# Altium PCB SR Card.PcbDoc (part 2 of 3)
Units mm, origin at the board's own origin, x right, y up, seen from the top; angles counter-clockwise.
Board outline 110.01 x 84.94 mm, 10 copper layers (Top Layer, Layer 2, Layer 3, Layer 4, Layer 5, Layer 6, Layer 7, Layer 8, Layer 9, Bottom Layer), stack 2.452 mm thick; 165 components, 84 nets, 582 pads, 1965 vias.
Unrouted connection lines stored in the file: 24.
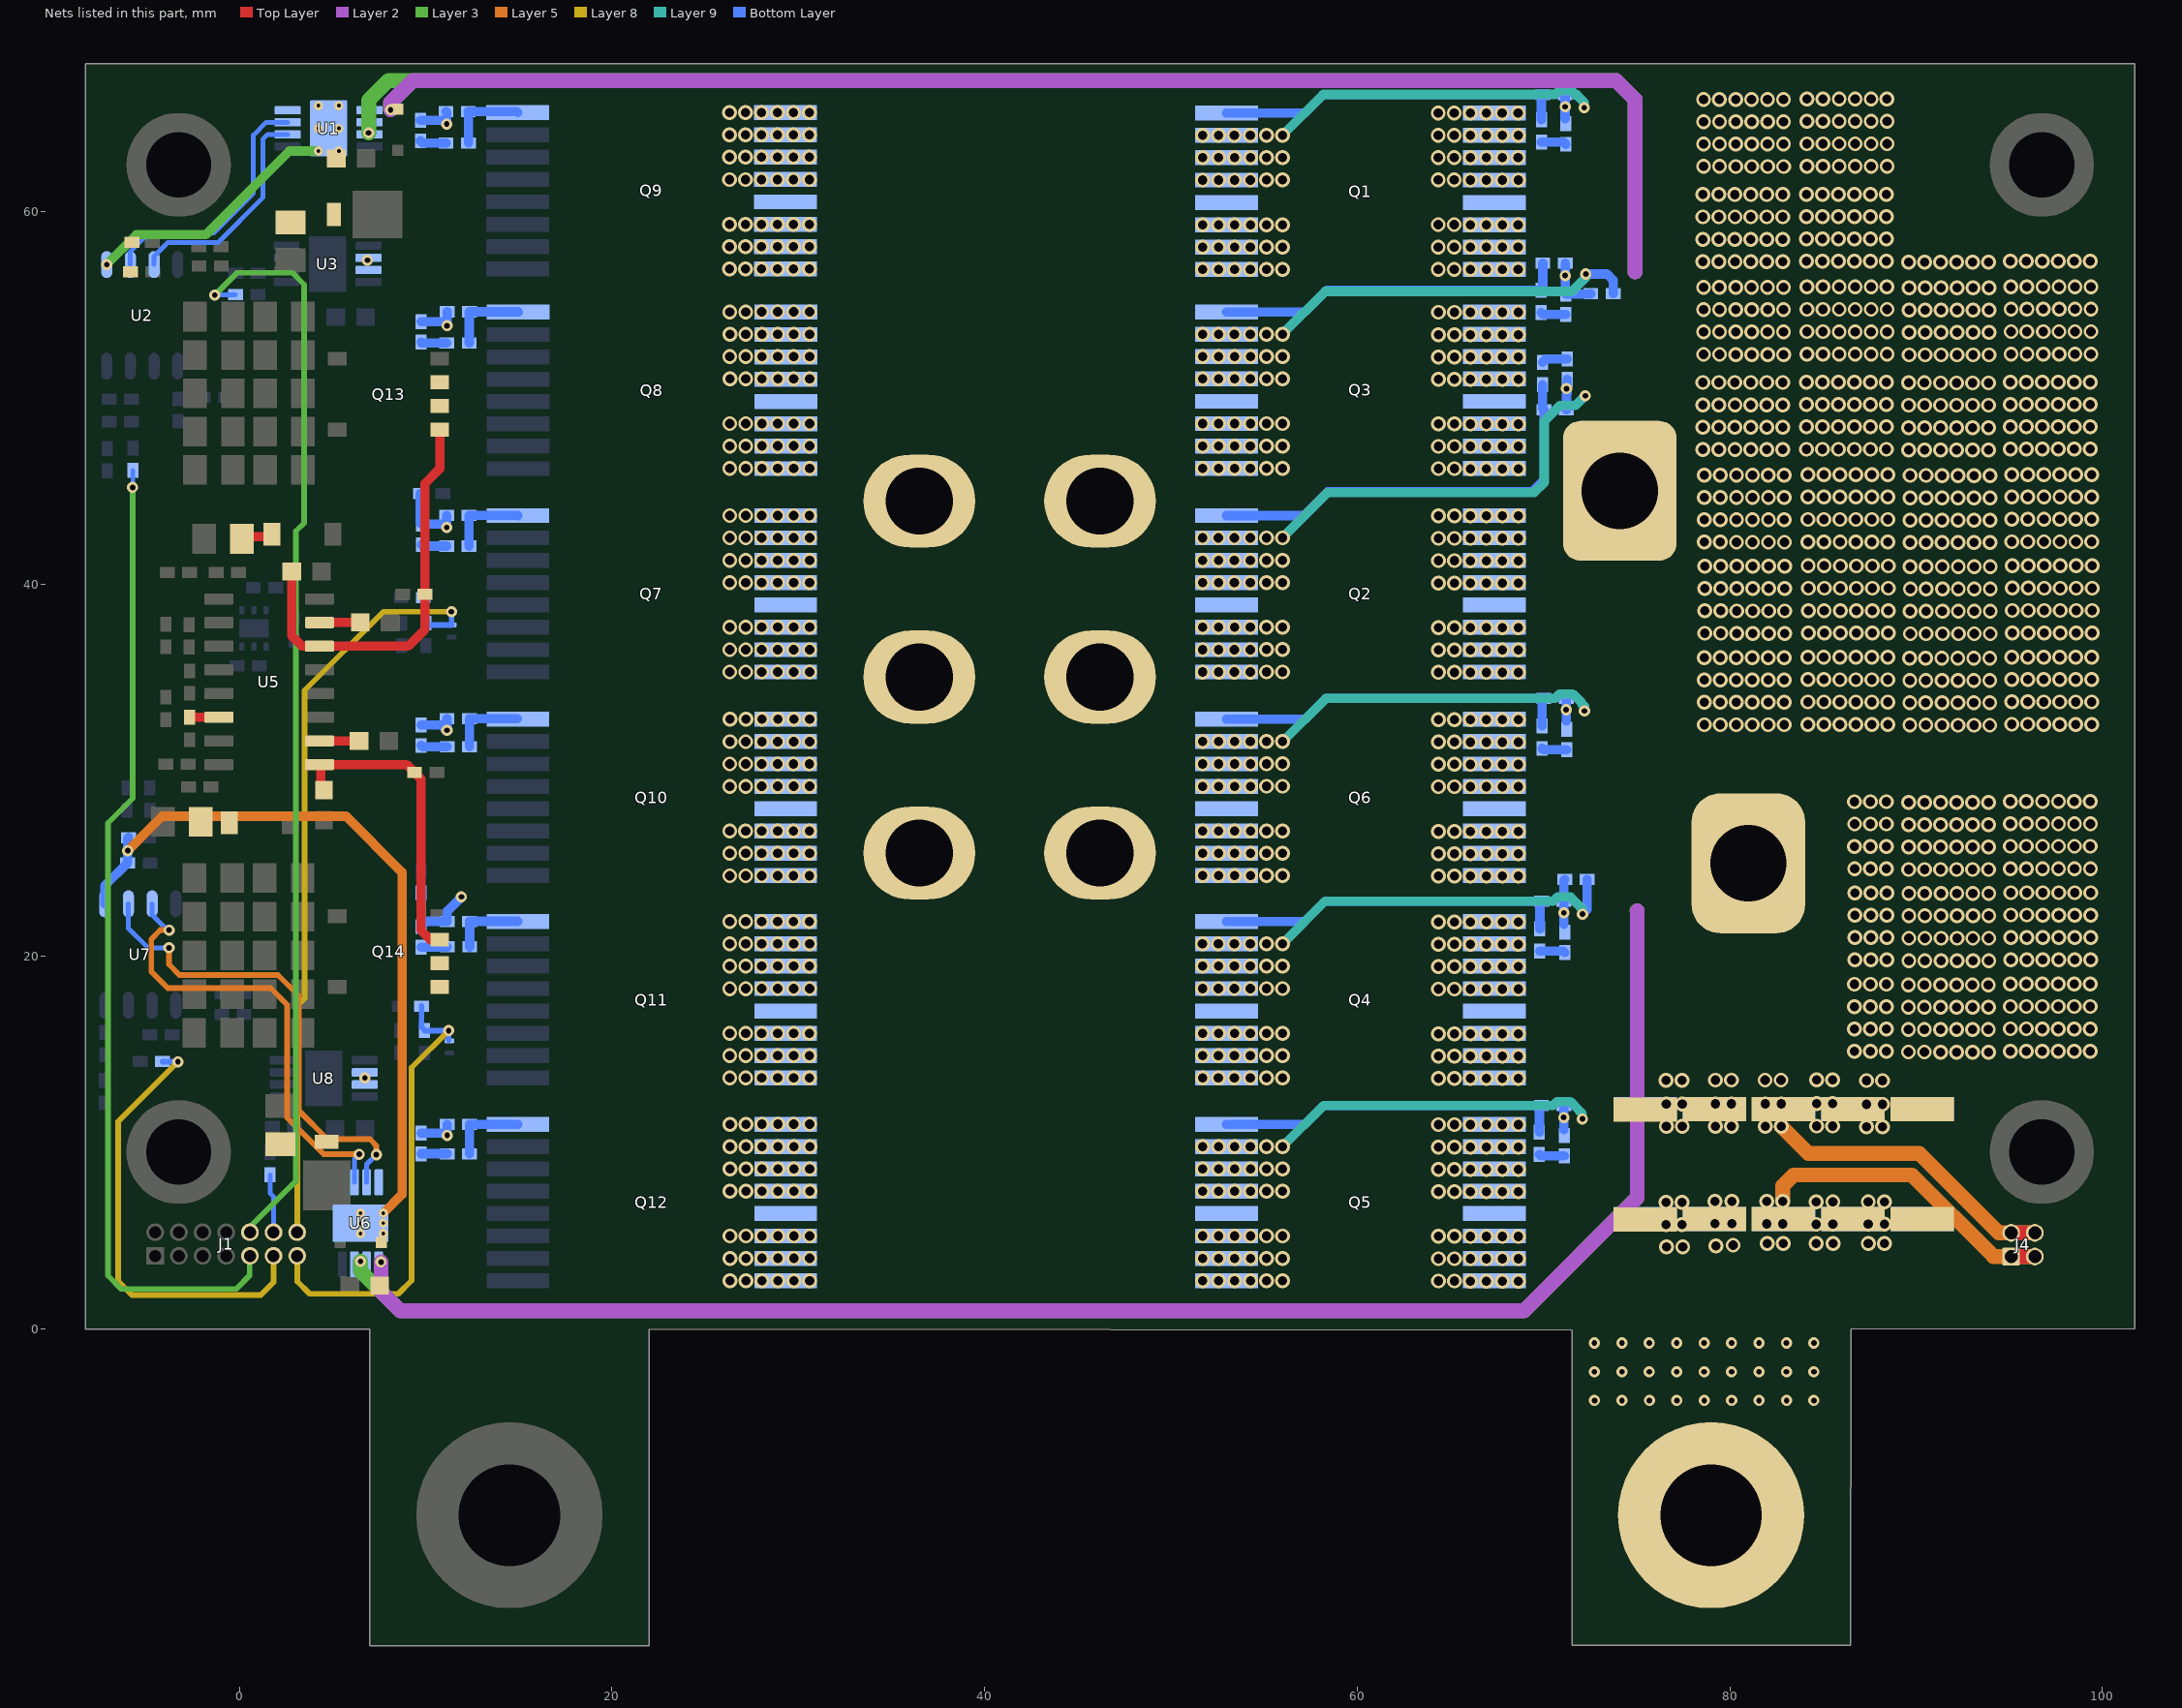
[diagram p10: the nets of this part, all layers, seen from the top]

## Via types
v1: diameter 0.8, hole 0.5, Top Layer to Bottom Layer, 1795 vias
v2: diameter 0.6, hole 0.3, Top Layer to Bottom Layer, 144 vias
v3: diameter 0.5, hole 0.2, Top Layer to Bottom Layer, 26 vias

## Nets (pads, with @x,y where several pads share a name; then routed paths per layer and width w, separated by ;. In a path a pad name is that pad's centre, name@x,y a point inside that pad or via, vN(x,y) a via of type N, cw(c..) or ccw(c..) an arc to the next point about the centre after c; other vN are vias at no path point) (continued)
NetD1_2: D1.2 R7.1 | length 3.1
  Top Layer w0.254: R7.1@0.146,42.426 0.383,42.663 D1.2@1.745,42.663
  Top Layer w0.5: R7.1@0.265,42.545 D1.2@1.628,42.545
NetD2_2: D2.2 R21.2
NetD3_2: D3.2 R35.1 | length 1.4
  Bottom Layer w0.5: R35.1@69.888,63.722 71.086,63.722 D3.2@71.203,63.604
NetD4_2: D4.2 R60.2 | length 1.4
  Bottom Layer w0.5: R60.2@69.926,31.169 69.998,31.098 D4.2@71.249,31.098
NetD5_2: D5.2 R63.1 | length 1.4
  Bottom Layer w0.5: R63.1@69.948,51.889 70.144,52.085 D5.2@71.281,52.085
NetD6_2: D6.2 R66.2 | length 1.4
  Bottom Layer w0.5: R66.2@69.781,9.367 69.855,9.294 D6.2@71.124,9.294
NetD7_2: D7.2 R62.1 | length 1.4
  Bottom Layer w0.5: R62.1@69.866,54.576 69.979,54.463 D7.2@71.2,54.463
NetD8_2: D8.2 R61.2 | length 1.4
  Bottom Layer w0.5: R61.2@69.807,20.28 71.066,20.28 D8.2@71.141,20.204
NetD9_2: D9.2 R64.1 | length 1.4
  Bottom Layer w0.5: D9.2@9.784,42.11 9.862,42.031 R64.1@11.126,42.031
NetD10_2: D10.2 R65.2 | length 1.4
  Bottom Layer w0.5: D10.2@9.767,9.409 R65.2@11.156,9.409
NetD11_2: D11.2 R67.1 | length 1.4
  Bottom Layer w0.5: D11.2@9.753,52.98 9.798,52.935 R67.1@11.142,52.935
NetD12_2: D12.2 R68.2 | length 1.4
  Bottom Layer w0.5: D12.2@9.756,20.502 11.156,20.502 R68.2@11.166,20.512
NetD13_2: D13.2 R70.1 | length 1.4
  Bottom Layer w0.5: D13.2@9.72,63.784 9.837,63.667 R70.1@11.097,63.667
NetD14_2: D14.2 R71.2 | length 1.4
  Bottom Layer w0.5: D14.2@9.765,31.324 9.829,31.26 R71.2@11.162,31.26
NetD15_2: D15.2 R5.1
NetD17_2: D17.2 R69.1
NetQ1_8: Q1.8 R1.2 R35.2 | length 18.8
  Bottom Layer w0.5: Q1.8@52.983,65.28 52.992,65.272 57.18,65.272 58.167,66.259 R1.2@69.963,66.259 69.888,66.183 R35.2@69.888,64.922
NetQ2_8: Q2.8 R9.2 R63.2 | length 23
  Bottom Layer w0.5: Q2.8@52.983,43.671 57.154,43.671 58.424,44.941 69.379,44.941 70.031,45.593 R9.2@70.031,49.34 69.948,49.423 R63.2@69.948,50.689
NetQ3_8: Q3.8 R15.2 R62.2 | length 18.8
  Bottom Layer w0.5: Q3.8@52.983,54.604 57.189,54.604 58.362,55.776 R62.2@69.866,55.776 69.965,55.876 R15.2@69.965,57.211
NetQ4_8: Q4.8 R16.1 R61.1 | length 18.9
  Bottom Layer w0.5: Q4.8@52.983,21.874 57.188,21.874 58.283,22.969 R16.1@69.9,22.969 69.807,22.876 R61.1@69.807,21.48
NetQ5_8: Q5.8 R10.1 R66.1 | length 18.8
  Bottom Layer w0.5: Q5.8@52.983,10.993 57.192,10.993 58.206,12.006 R10.1@69.885,12.006 69.781,11.902 R66.1@69.781,10.567
NetQ6_8: Q6.8 R2.1 R60.1 | length 19
  Bottom Layer w0.5: Q6.8@52.983,32.734 57.191,32.734 58.309,33.852 R2.1@70.016,33.852 69.926,33.762 R60.1@69.926,32.369
NetQ7_8: Q7.8 R30.2 R64.2 | length 4.3
  Bottom Layer w0.5: R64.2@12.326,42.031 12.326,43.674 R30.2@12.337,43.685 14.939,43.685 Q7.8@14.954,43.671
NetQ8_8: Q8.8 R36.2 R67.2 | length 4.3
  Bottom Layer w0.5: R67.2@12.342,52.935 12.342,54.601 R36.2@12.35,54.609 14.954,54.609 Q8.8@14.976,54.588
NetQ9_8: Q9.8 R42.2 R70.2 | length 4.4
  Bottom Layer w0.5: R70.2@12.297,63.667 12.297,65.36 R42.2@12.293,65.365 14.891,65.365 Q9.8@14.946,65.31
NetQ10_8: Q10.8 R39.1 R71.1 | length 4.1
  Bottom Layer w0.5: R71.1@12.362,31.26 12.362,32.749 R39.1@12.346,32.764 Q10.8@14.924,32.764
NetQ11_8: Q11.8 R33.1 R68.1 | length 4
  Bottom Layer w0.5: R68.1@12.366,20.512 12.366,21.883 R33.1@12.364,21.884 14.944,21.884 Q11.8@14.954,21.874
NetQ12_8: Q12.8 R26.1 R65.1 | length 4.2
  Bottom Layer w0.5: R65.1@12.356,9.409 R26.1@12.356,10.992 ; R26.1@12.356,10.992 Q12.8@14.954,10.993
NetR18_1: R18.1 U5.15 | length 2.2
  Top Layer w0.5: U5.15@4.306,37.924 4.325,37.943 R18.1@6.491,37.943
NetR37_1: R37.1 U5.10 | length 2.1
  Top Layer w0.5: U5.10@4.306,31.574 6.424,31.574 R37.1@6.432,31.566
NetR51_1: R51.1 U5.6 | length 1.6
  Top Layer w0.5: R51.1@-2.679,32.836 -2.671,32.844 U5.6@-1.094,32.844
NetU1_2: U1.2 U2.7 | length 12.2
  Bottom Layer w0.254: U2.7@-4.576,57.144 -4.576,57.578 -3.828,58.326 -1.141,58.326 1.263,60.73 1.263,63.874 1.52,64.131 U1.2@2.597,64.131
NetU1_3: U1.3 U2.6 | length 13.8
  Bottom Layer w0.254: U2.6@-5.846,57.144 -5.846,57.846 -4.86,58.832 -1.377,58.832 0.757,60.966 0.757,64.088 1.449,64.781 U1.3@2.597,64.781
NetU6_2: U6.2 U7.7 | length 25.1
  Layer 5 w0.3: v2(-3.769,21.416) -4.239,21.416 -4.722,20.933 -4.722,19.182 -3.837,18.296 1.682,18.296 2.571,17.407 2.571,11.345 4.527,9.39 4.527,9.383 v2(6.437,9.383)
  Bottom Layer w0.254: U7.7@-4.678,22.824 -4.678,22.225 v2@-3.819,21.366 ; U6.2@6.184,7.871 6.184,9.131 v2(6.437,9.383)
NetU6_3: U6.3 U7.6 | length 25.8
  Layer 5 w0.3: v2(-3.772,20.461) -3.772,19.57 -3.211,19.009 2.079,19.009 3.209,17.879 3.209,11.712 4.733,10.188 7.008,10.188 7.355,9.841 v2(7.355,9.36)
  Bottom Layer w0.254: U7.6@-5.948,22.824 -5.948,21.497 -4.912,20.461 v2(-3.772,20.461) ; U6.3@6.834,7.871 6.834,8.839 v2(7.355,9.36)
"SR1 HO": D3.1 D5.1 D7.1 R1.1 R9.1 R11.2 R15.1 U1.6 U1.7 | length 85.4
  Layer 3 w0.8: v2(6.941,64.214) 6.941,65.957 8.013,67.029 73.9,67.029 74.908,66.021 74.908,56.76
  Bottom Layer w0.5: D3.1@71.163,64.982 v2(71.163,65.62) R1.1@71.163,66.259 ; D7.1@71.165,55.895 v2(71.165,56.553) R15.1@71.165,57.211 ; D7.1@71.2,55.563 72.516,55.563 R11.2@72.539,55.586 ; R9.1@71.231,49.34 71.238,49.347 71.238,50.183 71.281,50.225 D5.1@71.281,50.985
  other v2: 71.238,50.483
"SR1 LO": D9.1 D11.1 D13.1 R30.1 R36.1 R42.1 R45.2 U3.6 U3.7 | length 8.2
  Bottom Layer w0.5: R45.2@9.719,44.858 9.719,43.274 D9.1@9.784,43.21 10.957,43.21 v2(11.137,43.029) R30.1@11.137,43.685 ; D13.1@9.72,64.884 10.942,64.884 v2(11.133,64.693) 11.133,65.325 R42.1@11.093,65.365 ; D11.1@9.753,54.08 10.933,54.08 v2(11.15,53.862) R36.1@11.15,54.609
  other v2: 6.882,57.384
SR1_HS_PWM: J1.9 R48.1 | length 53.1
  Layer 3 w0.3: v2(-5.723,45.181) -5.723,28.488 -7.051,27.16 -7.051,2.865 -6.339,2.152 -0.161,2.152 0.559,2.872 0.559,3.916 J1.9@0.569,3.926
  Bottom Layer w0.24: v2(-5.723,45.181) -5.715,45.189 R48.1@-5.715,46.102
SR1_LS_PWM: J1.10 R12.1 | length 58.8
  Layer 3 w0.3: v2(-1.316,55.509) -0.122,56.703 2.849,56.703 3.481,56.071 3.481,43.266 3.044,42.829 3.044,7.947 0.569,5.472 J1.10@0.569,5.196
  Bottom Layer w0.24: v2(-1.316,55.509) -1.306,55.518 -0.213,55.518 R12.1@-0.203,55.528
"SR2 HO": D4.1 D6.1 D8.1 R2.2 R10.2 R14.1 R16.2 U6.6 U6.7 | length 92.8
  Layer 3 w0.8: v2(6.503,3.626) 6.503,3.123 8.657,0.969 68.939,0.969 75.032,7.063 75.032,22.446 75.023,22.454
  Bottom Layer w0.5: D6.1@71.085,10.713 v2(71.085,11.36) R10.2@71.085,12.006 ; 71.1,21.716 v2(71.1,22.343) R16.2@71.1,22.969 71.1,24.091 R14.1@71.149,24.14 ; 71.216,32.64 v2(71.216,33.246) R2.2@71.216,33.852
"SR2 LO": D10.1 D12.1 D14.1 R26.2 R33.2 R39.2 R54.1 U8.6 U8.7 | length 9.1
  Bottom Layer w0.5: R54.1@9.755,23.398 9.755,21.603 D12.1@9.756,21.602 10.039,21.884 R33.2@11.164,21.884 11.164,22.438 v2(11.922,23.195) ; D14.1@9.765,32.424 10.86,32.424 v2(11.146,32.138) R39.2@11.146,32.764 ; D10.1@9.767,10.509 11.044,10.509 v2(11.156,10.397) R26.2@11.156,10.992
  other v2: 6.741,13.478
SR2_HS_PWM: J1.11 R49.1 | length 24.1
  Layer 8 w0.3: v2(-3.293,14.344) -6.5,11.138 -6.5,2.567 -5.754,1.822 1.149,1.822 1.839,2.511 J1.11@1.839,3.926
  Bottom Layer w0.3: R49.1@-4.126,14.355 v2@-3.507,14.355
SR2_LS_PWM: J1.12 R53.1 | length 3.2
  Bottom Layer w0.254: R53.1@1.657,8.277 1.657,7.284 1.831,7.109 1.833,7.109 1.839,7.103 J1.12@1.839,5.196
T_LV_1: C28.1 J1.13 R44.1 RT1.2 | length 25.5
  Layer 8 w0.3: J1.13@3.109,3.926 3.109,2.557 3.781,1.885 8.529,1.885 9.247,2.603 9.247,14.033 v2(11.233,16.02)
  Bottom Layer w0.3: R44.1@9.781,17.335 9.781,16.206 C28.1@9.945,16.043 ; C28.1@9.945,16.02 v2(11.233,16.02) RT1.2@11.233,15.51
T_LV_2: C19.1 J1.14 R22.1 RT2.2 | length 42.4
  Layer 8 w0.3: J1.14@3.109,5.196 3.109,17.346 3.511,17.747 3.511,34.281 7.735,38.506 v2(11.382,38.506)
  Bottom Layer w0.3: R22.1@9.876,39.256 9.876,38.027 C19.1@10.007,37.895 10.108,37.794 RT2.2@11.407,37.794 ; v2(11.382,38.506) 11.39,38.498 RT2.2@11.39,37.82
VBIAS: J2.1 J4.1 J4.3 R29.2 R40.2 R41.2 R46.2 R47.2 R50.2 R56.2 R57.2 R58.2 R59.2 | length 17.7
  Top Layer w0.8: J4.1@95.102,3.891 J4.3@96.372,3.891
  Layer 5 w0.8: v1(82.85,6.843) 82.85,7.696 83.422,8.269 89.777,8.269 94.155,3.891 J4.1@95.102,3.891 J4.3@96.372,3.891
  other v1: 76.61,4.404 77.476,4.402 79.252,4.463 80.176,4.499 82.013,4.582 82.869,4.582 84.631,4.582 85.537,4.589 87.433,4.6 88.298,4.598 76.574,5.605 77.43,5.605 84.628,5.616 85.534,5.623 79.199,5.647 81.995,5.641 82.852,5.641 87.43,5.634 88.295,5.632 80.107,5.654 76.572,6.805 77.429,6.805 84.627,6.818 81.994,6.843 85.532,6.823 87.428,6.834 88.293,6.832 79.197,6.847 80.105,6.856
  other v2: 72.741,-3.837 74.213,-3.837 75.685,-3.837 77.157,-3.837 78.629,-3.837 80.101,-3.837 81.574,-3.837 83.046,-3.837 84.518,-3.837 72.736,-2.295 74.208,-2.295 75.68,-2.295 77.153,-2.295 78.625,-2.295 80.097,-2.295 81.569,-2.295 83.041,-2.295 84.514,-2.295 72.736,-0.75 74.208,-0.75 75.68,-0.75 77.153,-0.75 78.625,-0.75 80.097,-0.75 81.569,-0.75 83.041,-0.75 84.514,-0.75
VOUT: J4.2 J4.4 pad.4@81,25 R29.1 R40.1 R41.1 R46.1 R47.1 R50.1 R56.1 R57.1 R58.1 R59.1 | length 17.3
  Top Layer w0.8: J4.2@95.102,5.161 J4.4@96.372,5.161
  Layer 5 w0.8: v1(82.759,10.884) 84.211,9.433 90.168,9.433 94.44,5.161 J4.2@95.102,5.161 J4.4@96.372,5.161
  other v1: 76.595,10.873 77.452,10.873 87.34,10.861 88.197,10.861 79.237,10.884 80.093,10.884 81.903,10.884 84.665,10.893 85.521,10.893 76.594,12.075 77.45,12.075 87.338,12.061 88.195,12.061 79.236,12.087 80.092,12.087 81.901,12.087 82.758,12.087 84.663,12.093 85.519,12.093 87.331,13.334 88.188,13.334 76.587,13.349 77.443,13.349 79.229,13.36 80.085,13.36 81.894,13.36 82.751,13.36 84.656,13.367 85.512,13.367 89.589,14.869 90.445,14.869 91.311,14.866 92.167,14.866 93.024,14.866 93.88,14.866 86.69,14.906 87.547,14.906 88.403,14.906 95.057,14.913 95.913,14.913 96.778,14.911 97.635,14.911 98.491,14.911 99.348,14.911 89.588,16.071 90.444,16.071 91.309,16.069 92.166,16.069 93.022,16.069 93.879,16.069 86.689,16.108 87.545,16.108 88.402,16.108 95.055,16.115 95.912,16.115 96.777,16.113 97.633,16.113 98.49,16.113 99.346,16.113 89.588,17.271 90.445,17.271 91.31,17.269 92.166,17.269 93.023,17.269 93.879,17.269 86.689,17.308 87.546,17.308 88.402,17.308 95.056,17.315 95.912,17.315 96.778,17.313 97.634,17.313 98.491,17.313 99.347,17.313 89.586,18.471 90.443,18.471 91.308,18.469 92.164,18.469 93.021,18.469 93.877,18.469 86.687,18.508 87.544,18.508 88.4,18.508 95.054,18.515 95.91,18.515 96.776,18.513 97.632,18.513 98.489,18.513 99.345,18.513 89.614,19.778 90.47,19.778 91.335,19.775 92.192,19.775 93.048,19.775 93.905,19.775 86.715,19.815 87.571,19.815 88.428,19.815 95.081,19.822 95.938,19.822 96.803,19.819 97.66,19.819 98.516,19.819 99.373,19.819 89.612,20.98 90.469,20.98 91.334,20.977 92.19,20.977 93.047,20.977 93.903,20.977 86.714,21.017 87.57,21.017 88.427,21.017 95.08,21.024 95.937,21.024 96.802,21.022 97.658,21.022 98.515,21.022 99.371,21.022 89.613,22.18 90.469,22.18 91.335,22.177 92.191,22.177 93.048,22.177 93.904,22.177 86.714,22.217 87.571,22.217 88.427,22.217 95.081,22.224 95.937,22.224 96.802,22.222 97.659,22.222 98.515,22.222 99.372,22.222 89.611,23.38 90.467,23.38 91.333,23.377 92.189,23.377 93.046,23.377 93.902,23.377 86.712,23.417 87.569,23.417 88.425,23.417 95.079,23.424 95.935,23.424 96.8,23.421 97.657,23.421 98.513,23.421 99.37,23.421 89.599,24.671 90.456,24.671 91.321,24.668 92.178,24.668 93.034,24.668 93.891,24.668 86.701,24.708 87.557,24.708 88.414,24.708 95.067,24.715 95.924,24.715 96.789,24.712 97.645,24.712 98.502,24.712 99.358,24.712 89.598,25.873 90.454,25.873 91.32,25.871 92.176,25.871 93.033,25.871 93.889,25.871 86.699,25.91 87.556,25.91 88.412,25.91 95.066,25.917 95.922,25.917 96.787,25.915 97.644,25.915 98.5,25.915 99.357,25.915 89.599,27.073 90.455,27.073 91.32,27.071 92.177,27.071 93.033,27.071 93.89,27.071 86.7,27.11 87.556,27.11 88.413,27.11 95.066,27.117 95.923,27.117 96.788,27.115 97.645,27.115 98.501,27.115 99.358,27.115 89.597,28.273 90.453,28.273 91.318,28.27 92.175,28.27 93.031,28.27 93.888,28.27 86.698,28.31 87.554,28.31 88.411,28.31 95.064,28.317 95.921,28.317 96.786,28.314 97.643,28.314 98.499,28.314 99.356,28.314
VSEC+: C2.2 C26.2 C29.2 D16.2 D19.2 pad.4@46.2,25.55 pad.4@46.2,35 pad.4@46.2,44.45 Q1.1 Q1.2 Q1.3 Q1.4 Q1.5 Q1.6 Q1.7 Q2.1 Q2.2 Q2.3 Q2.4 Q2.5 Q2.6 Q2.7 Q3.1 Q3.2 Q3.3 Q3.4 Q3.5 Q3.6 Q3.7 Q7.9 Q7.10 Q7.11 Q7.12 Q7.13 Q7.14 Q7.15 Q7.16 Q8.9 Q8.10 Q8.11 Q8.12 Q8.13 Q8.14 Q8.15 Q8.16 Q9.9 Q9.10 Q9.11 Q9.12 Q9.13 Q9.14 Q9.15 Q9.16 Q13.1 Q13.2 Q13.3 R3.1 R11.1 U1.4 U1.5 U1.9 U2.5 U5.14 | length 172.6
  Top Layer w0.5: C26.2@2.821,40.661 2.821,37.204 3.371,36.654 U5.14@4.306,36.654 9.062,36.654 9.973,37.565 R3.1@9.973,39.454 9.973,45.395 10.761,46.183 Q13.1@10.761,48.28
  Layer 2 w0.8: v2(8.114,65.455) 8.117,65.858 8.145,65.858 9.316,67.029 73.9,67.029 74.908,66.021 74.908,56.76
  Layer 3 w0.5: v2(-7.116,57.144) -5.514,58.746 -1.803,58.746 2.687,63.236 v3(4.247,63.236)
  Layer 9 w0.5: v1(55.991,42.473) 58.424,44.907 69.504,44.907 70.044,45.447 70.044,48.742 70.881,49.578 71.717,49.578 v2(72.245,50.106) ; v1(55.992,53.407) 58.289,55.703 71.518,55.703 72.275,56.461 v2(72.275,56.638) ; v1(55.992,64.084) 58.191,66.283 70.623,66.283 70.811,66.47 71.515,66.47 71.754,66.231 71.782,66.259 72.182,65.858 v2(72.182,65.56)
  Bottom Layer w0.5: v2(72.275,56.638) 73.413,56.638 73.739,56.312 R11.1@73.739,55.586
  other v1: 26.326,35.272 27.183,35.272 28.042,35.272 28.899,35.272 29.755,35.272 30.612,35.272 51.697,35.27 52.554,35.27 53.41,35.27 54.267,35.27 55.135,35.273 55.992,35.273 26.326,36.47 27.183,36.47 28.042,36.471 28.899,36.471 29.755,36.471 30.612,36.471 51.697,36.47 52.554,36.47 53.41,36.47 54.267,36.47 55.135,36.473 55.992,36.473 26.326,37.67 27.183,37.67 28.042,37.67 28.899,37.67 29.755,37.67 30.612,37.67 51.699,37.671 52.555,37.671 53.412,37.671 54.268,37.671 55.137,37.674 55.993,37.674 26.328,40.068 27.184,40.068 28.043,40.068 28.9,40.068 29.756,40.068 30.613,40.068 51.697,40.07 52.554,40.07 53.41,40.07 54.267,40.07 55.135,40.073 55.992,40.073 26.326,41.27 27.183,41.27 28.042,41.271 28.899,41.271 29.755,41.271 30.612,41.271 51.698,41.27 52.555,41.27 53.411,41.27 54.268,41.27 55.136,41.273 55.993,41.273 26.327,42.47 27.183,42.47 28.043,42.471 28.899,42.471 29.756,42.471 30.612,42.471 51.696,42.47 52.553,42.47 53.409,42.47 54.266,42.47 55.134,42.473 26.325,43.67 27.181,43.67 28.041,43.671 28.897,43.671 29.754,43.671 30.61,43.671 26.328,46.208 27.185,46.208 28.044,46.209 28.901,46.209 29.757,46.209 30.614,46.209 51.699,46.204 52.556,46.204 53.412,46.204 54.269,46.204 55.137,46.207 55.994,46.207 26.328,47.407 27.185,47.407 28.044,47.408 28.901,47.408 29.757,47.408 30.614,47.408 51.699,47.403 52.556,47.403 53.412,47.403 54.269,47.403 55.137,47.407 55.994,47.407 26.328,48.607 27.185,48.607 28.044,48.607 28.901,48.607 29.757,48.607 30.614,48.607 51.7,48.605 52.557,48.605 53.413,48.605 54.27,48.605 55.138,48.608 55.995,48.608 26.33,51.005 27.186,51.005 28.046,51.005 28.902,51.005 29.759,51.005 30.615,51.005 51.699,51.004 52.556,51.004 53.412,51.004 54.269,51.004 55.137,51.007 55.994,51.007 26.328,52.207 27.185,52.207 28.044,52.208 28.901,52.208 29.757,52.208 30.614,52.208 51.7,52.204 52.556,52.204 53.413,52.204 54.269,52.204 55.138,52.207 55.994,52.207 26.329,53.407 27.185,53.407 28.045,53.408 28.901,53.408 29.758,53.408 30.614,53.408 51.698,53.404 52.554,53.404 53.411,53.404 54.267,53.404 55.136,53.407 26.327,54.607 27.183,54.607 28.043,54.608 28.899,54.608 29.756,54.608 30.612,54.608 51.699,56.881 52.555,56.881 53.412,56.881 54.268,56.881 55.137,56.884 55.993,56.884 26.318,56.91 27.174,56.91 28.034,56.911 28.89,56.911 29.747,56.911 30.603,56.911 51.699,58.08 52.555,58.08 53.412,58.08 54.268,58.08 55.137,58.084 55.993,58.084 26.318,58.109 27.174,58.109 28.034,58.109 28.89,58.109 29.747,58.109 30.603,58.109 51.7,59.281 52.557,59.281 53.413,59.281 54.27,59.281 55.138,59.285 55.995,59.285 26.318,59.308 27.174,59.308 28.034,59.309 28.89,59.309 29.747,59.309 30.603,59.309 51.699,61.681 52.555,61.681 53.412,61.681 54.268,61.681 26.319,61.706 27.176,61.706 28.035,61.707 28.892,61.707 29.748,61.707 30.605,61.707 55.137,61.684 55.993,61.684 51.7,62.881 52.556,62.881 53.413,62.881 54.269,62.881 55.138,62.884 55.994,62.884 26.318,62.909 27.174,62.909 28.034,62.909 28.89,62.909 29.747,62.909 30.603,62.909 51.698,64.081 52.554,64.081 53.411,64.081 54.267,64.081 55.136,64.084 26.318,64.109 27.175,64.109 28.034,64.109 28.891,64.109 29.747,64.109 30.604,64.109 26.317,65.303 27.173,65.303 28.033,65.303 28.889,65.303 29.746,65.303 30.602,65.303
  other v3: 5.347,63.236 4.247,64.456 5.347,64.456 4.247,65.676 5.347,65.676
VSEC-: C8.2 C16.2 C37.2 D18.2 D20.2 pad.4@36.5,25.55 pad.4@36.5,35 pad.4@36.5,44.45 Q4.1 Q4.2 Q4.3 Q4.4 Q4.5 Q4.6 Q4.7 Q5.1 Q5.2 Q5.3 Q5.4 Q5.5 Q5.6 Q5.7 Q6.1 Q6.2 Q6.3 Q6.4 Q6.5 Q6.6 Q6.7 Q10.9 Q10.10 Q10.11 Q10.12 Q10.13 Q10.14 Q10.15 Q10.16 Q11.9 Q11.10 Q11.11 Q11.12 Q11.13 Q11.14 Q11.15 Q11.16 Q12.9 Q12.10 Q12.11 Q12.12 Q12.13 Q12.14 Q12.15 Q12.16 Q14.1 Q14.2 Q14.3 R4.1 R14.2 U5.9 U6.4 U6.5 U6.9 U7.5 | length 198.5
  Top Layer w0.5: C8.2@4.377,28.97 4.377,30.234 U5.9@4.306,30.304 8.985,30.304 R4.1@9.404,29.885 9.754,29.535 9.754,29.398 9.757,29.395 9.757,21.397 10.253,20.901 Q14.3@10.754,20.901
  Layer 2 w0.8: v2(7.611,3.596) 7.611,2.015 8.657,0.969 68.963,0.969 75.032,7.038 75.032,22.446
  Layer 5 w0.5: v2(-5.987,25.68) -4.142,27.525 5.73,27.525 8.737,24.517 8.737,7.229 v3(7.729,6.221)
  Layer 9 w0.5: v1(55.99,20.677) 58.283,22.969 70.525,22.969 70.748,23.193 71.452,23.193 71.95,22.695 71.95,22.675 72.096,22.529 v2(72.096,22.271) ; v1(55.994,9.794) 58.206,12.006 70.53,12.006 70.733,12.21 71.437,12.21 71.935,11.712 71.935,11.696 72.092,11.538 v2(72.092,11.279) ; v1(55.994,31.537) 58.309,33.852 70.62,33.852 70.864,34.096 71.568,34.096 72.066,33.599 72.066,33.558 72.199,33.426 v2(72.199,33.181)
  Bottom Layer w0.5: U7.5@-7.218,22.824 -7.218,23.798 C37.2@-5.987,25.028 v2(-5.987,25.68) -5.987,26.332 D20.2@-5.937,26.382 ; v2(72.096,22.271) 72.349,22.524 R14.2@72.349,24.14
  other v1: 26.332,2.596 27.188,2.596 28.047,2.596 28.904,2.596 29.76,2.596 30.617,2.596 51.701,2.591 52.557,2.591 53.414,2.591 54.27,2.591 55.139,2.594 55.995,2.594 26.332,3.794 27.188,3.794 28.047,3.795 28.904,3.795 29.76,3.795 30.617,3.795 51.701,3.791 52.557,3.791 53.414,3.791 54.27,3.791 55.139,3.794 55.995,3.794 26.332,4.994 27.188,4.994 28.047,4.995 28.904,4.995 29.76,4.995 30.617,4.995 51.702,4.992 52.559,4.992 53.415,4.992 54.272,4.992 55.14,4.995 55.997,4.995 26.333,7.392 27.189,7.392 28.049,7.393 28.905,7.393 29.762,7.393 30.618,7.393 51.701,7.391 52.557,7.391 53.414,7.391 54.27,7.391 55.139,7.394 55.995,7.394 26.332,8.594 27.188,8.594 28.047,8.595 28.904,8.595 29.76,8.595 30.617,8.595 51.701,8.591 52.558,8.591 53.414,8.591 54.271,8.591 55.139,8.594 55.996,8.594 51.699,9.791 52.556,9.791 53.412,9.791 54.269,9.791 26.332,9.794 27.189,9.794 28.048,9.795 28.905,9.795 29.761,9.795 30.618,9.795 55.137,9.794 26.33,10.994 27.187,10.994 28.046,10.995 28.903,10.995 29.759,10.995 30.616,10.995 51.697,13.474 52.554,13.474 53.41,13.474 54.267,13.474 26.325,13.476 27.182,13.476 28.041,13.476 28.898,13.476 29.754,13.476 30.611,13.476 55.135,13.477 55.992,13.477 26.325,14.674 27.182,14.674 28.041,14.675 28.898,14.675 29.754,14.675 30.611,14.675 51.697,14.673 52.554,14.673 53.41,14.673 54.267,14.673 55.135,14.677 55.992,14.677 26.325,15.874 27.182,15.874 28.041,15.875 28.898,15.875 29.754,15.875 30.611,15.875 51.698,15.874 52.555,15.874 53.411,15.874 54.268,15.874 55.136,15.878 55.993,15.878 26.327,18.272 27.183,18.272 28.043,18.273 28.899,18.273 29.756,18.273 30.612,18.273 51.697,18.274 52.554,18.274 53.41,18.274 54.267,18.274 55.135,18.277 55.992,18.277 26.325,19.474 27.182,19.474 28.041,19.475 28.898,19.475 29.754,19.475 30.611,19.475 51.698,19.474 52.554,19.474 53.411,19.474 54.267,19.474 55.136,19.477 55.992,19.477 26.326,20.674 27.183,20.674 28.042,20.675 28.898,20.675 29.755,20.675 30.611,20.675 51.696,20.673 52.552,20.673 53.409,20.673 54.265,20.673 55.134,20.677 26.324,21.874 27.181,21.874 28.04,21.875 28.896,21.875 29.753,21.875 30.609,21.875 26.324,24.332 27.181,24.332 28.04,24.333 28.896,24.333 29.753,24.333 30.609,24.333 51.701,24.334 52.557,24.334 53.414,24.334 54.27,24.334 55.139,24.337 55.995,24.337 26.326,25.532 27.182,25.532 28.042,25.533 28.898,25.533 29.755,25.533 30.611,25.533 51.701,25.534 52.557,25.534 53.414,25.534 54.27,25.534 55.139,25.537 55.995,25.537 26.324,26.733 27.18,26.733 28.04,26.733 28.896,26.733 29.753,26.733 30.609,26.733 51.702,26.735 52.559,26.735 53.415,26.735 54.272,26.735 55.14,26.738 55.997,26.738 26.326,29.135 27.182,29.135 28.042,29.136 28.898,29.136 29.755,29.136 30.611,29.136 51.701,29.134 52.557,29.134 53.414,29.134 54.27,29.134 55.139,29.138 55.995,29.138 26.324,30.335 27.181,30.335 28.04,30.336 28.897,30.336 29.753,30.336 30.61,30.336 51.701,30.334 52.558,30.334 53.414,30.334 54.271,30.334 55.139,30.338 55.996,30.338 26.329,31.531 27.185,31.531 28.045,31.532 28.901,31.532 29.758,31.532 30.614,31.532 51.699,31.534 52.556,31.534 53.412,31.534 54.269,31.534 55.137,31.537 26.331,32.737 27.187,32.737 28.047,32.738 28.903,32.738 29.76,32.738 30.616,32.738
  other v3: 6.509,5.121 7.729,5.121 6.509,5.671 7.727,5.68 6.509,6.221
VSR: pad.4@74.1,45 Q1.9 Q1.10 Q1.11 Q1.12 Q1.13 Q1.14 Q1.15 Q1.16 Q2.9 Q2.10 Q2.11 Q2.12 Q2.13 Q2.14 Q2.15 Q2.16 Q3.9 Q3.10 Q3.11 Q3.12 Q3.13 Q3.14 Q3.15 Q3.16 Q4.9 Q4.10 Q4.11 Q4.12 Q4.13 Q4.14 Q4.15 Q4.16 Q5.9 Q5.10 Q5.11 Q5.12 Q5.13 Q5.14 Q5.15 Q5.16 Q6.9 Q6.10 Q6.11 Q6.12 Q6.13 Q6.14 Q6.15 Q6.16
  other v1: 64.364,2.574 65.221,2.574 66.086,2.571 66.942,2.571 67.799,2.571 68.655,2.571 66.086,3.77 66.942,3.77 67.799,3.77 68.655,3.77 64.364,3.773 65.221,3.773 64.364,4.972 65.221,4.972 66.086,4.97 66.942,4.97 67.799,4.97 68.655,4.97 64.365,7.37 65.222,7.37 66.087,7.368 66.944,7.368 67.8,7.368 68.657,7.368 66.086,8.57 66.942,8.57 67.799,8.57 68.655,8.57 64.364,8.573 65.221,8.573 64.365,9.773 65.221,9.773 66.086,9.77 66.943,9.77 67.799,9.77 68.656,9.77 64.363,10.972 65.219,10.972 66.084,10.97 66.941,10.97 67.797,10.97 68.654,10.97 64.358,13.454 65.214,13.454 66.08,13.451 66.936,13.451 67.793,13.451 68.649,13.451 64.358,14.652 65.214,14.652 66.08,14.65 66.936,14.65 67.793,14.65 68.649,14.65 64.358,15.852 65.214,15.852 66.08,15.85 66.936,15.85 67.793,15.85 68.649,15.85 66.081,18.248 66.937,18.248 67.794,18.248 68.65,18.248 64.359,18.25 65.216,18.25 64.358,19.452 65.214,19.452 66.08,19.45 66.936,19.45 67.793,19.45 68.649,19.45 64.359,20.652 65.215,20.652 66.08,20.65 66.937,20.65 67.793,20.65 68.65,20.65 64.357,21.852 65.213,21.852 66.078,21.85 66.935,21.85 67.791,21.85 68.648,21.85 64.357,24.311 65.213,24.311 66.078,24.308 66.935,24.308 67.791,24.308 68.648,24.308 64.358,25.51 65.215,25.51 66.08,25.508 66.937,25.508 67.793,25.508 68.65,25.508 64.356,26.711 65.213,26.711 66.078,26.708 66.935,26.708 67.791,26.708 68.648,26.708 64.358,29.114 65.215,29.114 66.08,29.111 66.937,29.111 67.793,29.111 68.65,29.111 64.357,30.313 65.213,30.313 66.079,30.311 66.935,30.311 67.791,30.311 68.648,30.311 66.083,31.507 66.939,31.507 67.796,31.507 68.652,31.507 64.361,31.509 65.218,31.509 89.665,32.419 90.521,32.419 91.387,32.416 92.243,32.416 93.1,32.416 93.956,32.416 78.63,32.441 79.486,32.441 80.351,32.439 81.208,32.439 82.064,32.439 82.921,32.439 84.188,32.458 85.044,32.458 85.91,32.456 86.766,32.456 87.623,32.456 88.479,32.456 95.133,32.463 95.989,32.463 96.854,32.461 97.711,32.461 98.567,32.461 99.424,32.461 64.363,32.716 65.22,32.716 66.085,32.713 66.941,32.713 67.798,32.713 68.654,32.713 80.35,33.641 81.207,33.641 82.063,33.641 82.92,33.641 89.663,33.621 90.52,33.621 91.385,33.619 92.242,33.619 93.098,33.619 93.955,33.619 78.628,33.643 79.485,33.643 84.187,33.661 85.043,33.661 85.908,33.658 86.765,33.658 87.621,33.658 88.478,33.658 95.131,33.665 95.988,33.665 96.853,33.663 97.709,33.663 98.566,33.663 99.422,33.663 89.664,34.821 90.521,34.821 91.386,34.819 92.242,34.819 93.099,34.819 93.955,34.819 78.629,34.843 79.486,34.843 80.351,34.841 81.207,34.841 82.064,34.841 82.92,34.841 84.187,34.861 85.044,34.861 85.909,34.858 86.765,34.858 87.622,34.858 88.478,34.858 95.132,34.865 95.988,34.865 96.854,34.863 97.71,34.863 98.567,34.863 99.423,34.863 64.359,35.25 65.215,35.25 66.08,35.247 66.937,35.247 67.793,35.247 68.65,35.247 89.662,36.021 90.519,36.021 91.384,36.019 92.24,36.019 93.097,36.019 93.953,36.019 78.627,36.043 79.484,36.043 80.349,36.041 81.205,36.041 82.062,36.041 82.918,36.041 84.185,36.061 85.042,36.061 85.907,36.058 86.763,36.058 87.62,36.058 88.476,36.058 95.13,36.065 95.986,36.065 96.852,36.063 97.708,36.063 98.565,36.063 99.421,36.063 64.359,36.448 65.215,36.448 66.08,36.446 66.937,36.446 67.793,36.446 68.65,36.446 91.411,37.325 92.268,37.325 93.124,37.325 93.981,37.325 78.655,37.35 79.511,37.35 80.376,37.347 81.233,37.347 82.089,37.347 82.946,37.347 89.69,37.328 90.546,37.328 84.213,37.367 85.069,37.367 85.934,37.365 86.791,37.365 87.647,37.365 88.504,37.365 95.157,37.372 96.014,37.372 96.879,37.369 97.736,37.369 98.592,37.369 99.449,37.369 64.359,37.648 65.215,37.648 66.08,37.646 66.937,37.646 67.793,37.646 68.65,37.646 89.688,38.53 90.545,38.53 91.41,38.527 92.266,38.527 93.123,38.527 93.979,38.527 78.653,38.552 79.51,38.552 80.375,38.55 81.231,38.55 82.088,38.55 82.944,38.55 84.211,38.569 85.068,38.569 85.933,38.567 86.79,38.567 87.646,38.567 88.503,38.567 95.156,38.574 96.013,38.574 96.878,38.572 97.734,38.572 98.591,38.572 99.447,38.572 89.689,39.73 90.545,39.73 91.411,39.727 92.267,39.727 93.124,39.727 93.98,39.727 78.654,39.752 79.51,39.752 80.375,39.75 81.232,39.75 82.088,39.75 82.945,39.75 84.212,39.769 85.068,39.769 85.934,39.767 86.79,39.767 87.647,39.767 88.503,39.767 95.157,39.774 96.013,39.774 96.878,39.772 97.735,39.772 98.591,39.772 99.448,39.772 64.36,40.046 65.217,40.046 66.082,40.044 66.938,40.044 67.795,40.044 68.651,40.044 89.687,40.93 90.543,40.93 91.409,40.927 92.265,40.927 93.122,40.927 93.978,40.927 78.652,40.952 79.508,40.952 80.374,40.949 81.23,40.949 82.087,40.949 82.943,40.949 84.21,40.969 85.067,40.969 85.932,40.967 86.788,40.967 87.645,40.967 88.501,40.967 95.155,40.974 96.011,40.974 96.876,40.971 97.733,40.971 98.589,40.971 99.446,40.971 64.359,41.248 65.215,41.248 66.08,41.246 66.937,41.246 67.793,41.246 68.65,41.246 89.675,42.221 90.532,42.221 91.397,42.218 92.254,42.218 93.11,42.218 93.966,42.218 78.64,42.243 79.497,42.243 80.362,42.24 81.218,42.24 82.075,42.24 82.931,42.24 84.198,42.26 85.055,42.26 85.92,42.258 86.777,42.258 87.633,42.258 88.49,42.258 95.143,42.265 96,42.265 96.865,42.262 97.721,42.262 98.578,42.262 99.434,42.262 64.359,42.448 65.216,42.448 66.081,42.446 66.938,42.446 67.794,42.446 68.651,42.446 91.396,43.421 92.252,43.421 93.109,43.421 93.965,43.421 78.639,43.445 79.495,43.445 80.361,43.443 81.217,43.443 82.074,43.443 82.93,43.443 89.674,43.423 90.53,43.423 84.197,43.463 85.054,43.463 85.919,43.46 86.775,43.46 87.632,43.46 88.488,43.46 95.142,43.467 95.998,43.467 96.863,43.465 97.72,43.465 98.576,43.465 99.433,43.465 64.357,43.648 65.214,43.648 66.079,43.646 66.936,43.646 67.792,43.646 68.649,43.646 89.675,44.623 90.531,44.623 91.396,44.621 92.253,44.621 93.109,44.621 93.966,44.621 78.64,44.645 79.496,44.645 80.361,44.643 81.218,44.643 82.074,44.643 82.931,44.643 84.198,44.663 85.054,44.663 85.919,44.66 86.776,44.66 87.632,44.66 88.489,44.66 96.864,44.665 97.721,44.665 98.577,44.665 99.434,44.665 95.142,44.667 95.999,44.667 89.673,45.823 90.529,45.823 91.394,45.82 92.251,45.82 93.107,45.82 93.964,45.82 78.638,45.845 79.494,45.845 80.359,45.842 81.216,45.842 82.072,45.842 82.929,45.842 84.196,45.862 85.052,45.862 85.917,45.86 86.774,45.86 87.63,45.86 88.487,45.86 95.14,45.867 95.997,45.867 96.862,45.864 97.719,45.864 98.575,45.864 99.432,45.864 64.361,46.187 65.217,46.187 66.083,46.184 66.939,46.184 67.796,46.184 68.652,46.184 89.594,47.192 90.451,47.192 91.316,47.189 92.172,47.189 93.029,47.189 93.885,47.189 78.559,47.214 79.416,47.214 80.281,47.211 81.137,47.211 81.994,47.211 82.85,47.211 84.117,47.231 84.974,47.231 85.839,47.229 86.695,47.229 87.552,47.229 88.408,47.229 95.062,47.236 95.918,47.236 96.784,47.233 97.64,47.233 98.497,47.233 99.353,47.233 66.083,47.383 66.939,47.383 67.796,47.383 68.652,47.383 64.361,47.385 65.217,47.385 89.593,48.394 90.449,48.394 91.315,48.392 92.171,48.392 93.027,48.392 93.884,48.392 78.558,48.416 79.414,48.416 80.279,48.414 81.136,48.414 81.992,48.414 82.849,48.414 84.116,48.434 84.972,48.434 85.838,48.431 86.694,48.431 87.551,48.431 88.407,48.431 95.061,48.438 95.917,48.438 96.782,48.436 97.639,48.436 98.495,48.436 99.352,48.436 64.361,48.585 65.217,48.585 66.083,48.582 66.939,48.582 67.796,48.582 68.652,48.582 91.315,49.592 92.172,49.592 93.028,49.592 93.885,49.592 78.558,49.616 79.415,49.616 80.28,49.614 81.137,49.614 81.993,49.614 82.85,49.614 89.593,49.594 90.45,49.594 84.117,49.634 84.973,49.634 85.838,49.631 86.695,49.631 87.551,49.631 88.408,49.631 95.061,49.638 95.918,49.638 96.783,49.636 97.639,49.636 98.496,49.636 99.352,49.636 89.591,50.794 90.448,50.794 91.313,50.791 92.17,50.791 93.026,50.791 93.883,50.791 78.556,50.816 79.413,50.816 80.278,50.813 81.135,50.813 81.991,50.813 82.848,50.813 84.115,50.833 84.971,50.833 85.836,50.831 86.693,50.831 87.549,50.831 88.406,50.831 95.059,50.838 95.916,50.838 96.781,50.835 97.637,50.835 98.494,50.835 99.35,50.835 64.362,50.983 65.219,50.983 66.084,50.981 66.94,50.981 67.797,50.981 68.653,50.981 66.083,52.183 66.939,52.183 67.796,52.183 68.652,52.183 64.361,52.185 65.217,52.185 89.629,52.3 90.485,52.3 91.35,52.297 92.207,52.297 93.063,52.297 93.92,52.297 78.594,52.322 79.45,52.322 80.315,52.319 81.172,52.319 82.028,52.319 82.885,52.319 84.152,52.339 85.008,52.339 85.874,52.337 86.73,52.337 87.587,52.337 88.443,52.337 95.097,52.344 95.953,52.344 96.818,52.341 97.675,52.341 98.531,52.341 99.388,52.341 64.361,53.385 65.218,53.385 66.083,53.383 66.94,53.383 67.796,53.383 68.653,53.383 89.627,53.502 90.484,53.502 91.349,53.5 92.206,53.5 93.062,53.5 93.919,53.5 78.592,53.524 79.449,53.524 80.314,53.522 81.171,53.522 82.027,53.522 82.884,53.522 84.151,53.542 85.007,53.542 85.872,53.539 86.729,53.539 87.585,53.539 88.442,53.539 95.095,53.546 95.952,53.546 96.817,53.544 97.673,53.544 98.53,53.544 99.386,53.544 64.36,54.585 65.216,54.585 66.081,54.583 66.938,54.583 67.794,54.583 68.651,54.583 78.593,54.724 79.449,54.724 80.315,54.722 81.171,54.722 82.028,54.722 82.884,54.722 89.628,54.702 90.485,54.702 91.35,54.7 92.206,54.7 93.063,54.7 93.919,54.7 84.151,54.742 85.008,54.742 85.873,54.739 86.729,54.739 87.586,54.739 88.442,54.739 95.096,54.746 95.952,54.746 96.818,54.744 97.674,54.744 98.531,54.744 99.387,54.744 89.626,55.902 90.483,55.902 91.348,55.899 92.204,55.899 93.061,55.899 93.917,55.899 78.591,55.924 79.448,55.924 80.313,55.921 81.169,55.921 82.026,55.921 82.882,55.921 84.149,55.941 85.006,55.941 85.871,55.939 86.727,55.939 87.584,55.939 88.44,55.939 96.816,55.943 97.672,55.943 98.529,55.943 99.385,55.943 95.094,55.946 95.95,55.946 64.35,56.888 65.207,56.888 66.072,56.886 66.929,56.886 67.785,56.886 68.641,56.886 89.594,57.281 90.451,57.281 91.316,57.279 92.172,57.279 93.029,57.279 93.885,57.279 78.559,57.303 79.416,57.303 80.281,57.301 81.137,57.301 81.994,57.301 82.85,57.301 84.117,57.321 84.974,57.321 85.839,57.318 86.695,57.318 87.552,57.318 88.408,57.318 95.062,57.325 95.918,57.325 96.784,57.323 97.64,57.323 98.497,57.323 99.353,57.323 64.35,58.087 65.207,58.087 66.072,58.084 66.929,58.084 67.785,58.084 68.641,58.084 78.558,58.506 79.414,58.506 80.279,58.503 81.136,58.503 81.992,58.503 82.849,58.503 84.116,58.523 84.972,58.523 85.838,58.521 86.694,58.521 87.551,58.521 88.407,58.521 64.35,59.287 65.207,59.287 66.072,59.284 66.929,59.284 67.785,59.284 68.641,59.284 78.558,59.706 79.415,59.706 80.28,59.703 81.137,59.703 81.993,59.703 82.85,59.703 84.117,59.723 84.973,59.723 85.838,59.721 86.695,59.721 87.551,59.721 88.408,59.721 78.556,60.905 79.413,60.905 80.278,60.903 81.135,60.903 81.991,60.903 82.848,60.903 85.836,60.92 86.693,60.92 87.549,60.92 88.406,60.92 84.115,60.923 84.971,60.923 66.073,61.682 66.93,61.682 67.786,61.682 68.643,61.682 64.352,61.685 65.208,61.685 78.594,62.411 79.45,62.411 80.315,62.409 81.172,62.409 82.028,62.409 82.885,62.409 84.152,62.429 85.008,62.429 85.874,62.426 86.73,62.426 87.587,62.426 88.443,62.426 64.35,62.887 65.207,62.887 66.072,62.884 66.929,62.884 67.785,62.884 68.641,62.884 78.592,63.614 79.449,63.614 80.314,63.611 81.171,63.611 82.027,63.611 82.884,63.611 84.151,63.631 85.007,63.631 85.872,63.629 86.729,63.629 87.585,63.629 88.442,63.629 64.351,64.087 65.207,64.087 66.073,64.084 66.929,64.084 67.786,64.084 68.642,64.084 78.593,64.814 79.449,64.814 80.315,64.811 81.171,64.811 82.028,64.811 82.884,64.811 84.151,64.831 85.008,64.831 85.873,64.829 86.729,64.829 87.586,64.829 88.442,64.829 64.349,65.287 65.205,65.287 66.071,65.284 66.927,65.284 67.784,65.284 68.64,65.284 78.591,66.013 79.448,66.013 80.313,66.011 81.169,66.011 82.026,66.011 82.882,66.011 84.149,66.031 85.006,66.031 85.871,66.028 86.727,66.028 87.584,66.028 88.44,66.028
pads on no net: LBL1.0 U4.5 U4.7@0.335,37.609 U4.7@1.235,37.609 U5.7 U5.12 U5.13

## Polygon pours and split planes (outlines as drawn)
DGND on Layer 6 "LAYER_6_DGND_P305" (solid, remove dead copper, pour order 305): 6.974,-16.999 22.001,-16.999 22.001,67.581 21.686,67.895 -8.268,67.895 -8.268,1.978 -6.395,0.105 6.974,0.105
VBIAS on Layer 6 "LAYER_6_VBIAS_P329" (solid, pour order 329): 90.97,0.022 92.375,0.022 93.908,1.555 93.908,7.879 93.095,8.693 71.987,8.693 71.518,6.854 71.518,-16.978 86.463,-16.978 86.463,0.058 86.5,0.022
VOUT on Layer 6 "LAYER_6_VOUT_P328" (solid, remove dead copper, pour order 328): 93.928,8.979 97.216,5.691 97.216,1.271 98.092,0.395 100.549,0.395 101.745,1.591 101.745,27.733 100.142,29.336 77.048,29.336 72.036,9.026
VSR on Layer 6 "LAYER_6_VSR_P292" (solid, remove dead copper, pour order 292): 100.189,29.553 101.746,31.102 101.746,65.958 100.159,67.544 60.72,67.544 60.72,1.857 71.315,1.857 71.315,6.854 76.847,29.373 77.05,29.538
VSEC+ on Layer 6 "LAYER_6_VSEC+_P249" (solid, pour order 249): 59.386,65.946 59.637,65.695 59.637,2.439 58.987,1.788 23.196,1.788 22.604,2.38 22.604,65.461 23.089,65.946
VSEC- on Layer 6 "LAYER_6_VSEC-_P248" (solid, pour order 248): 40.395,46.429 45.236,41.588 49.521,41.588 51.629,39.48 59.637,39.48 59.637,2.439 58.987,1.788 23.196,1.788 22.604,2.38 22.604,46.429
no net on Top Solder "NONET_L-01_P-001" (solid): 6.275,6.833 6.286,6.822 6.286,5.371 7.953,5.371 8.043,5.461 8.043,6.79 7.824,7.009 6.451,7.009
no net on Top Solder "NONET_L-01_P-001" (solid): 71.5,0 86.5,0 86.5,-16.978 71.5,-16.978
no net on Top Solder "NONET_L-01_P-001" (solid): 7,0 22,0 22,-16.999 7,-16.999
no net on Bottom Solder "NONET_L-01_P-001" (solid): 71.5,0 86.5,0 86.5,-16.999 71.5,-16.999
no net on Bottom Solder "NONET_L-01_P-001" (solid): 7,0 22,0 22,-16.999 7,-16.999
DGND on Layer 8 "LAYER_8_DGND_P307" (solid, remove dead copper, pour order 307): 6.974,-16.999 22.001,-16.999 22.001,67.581 21.686,67.895 -8.263,67.895 -8.263,1.973 -6.395,0.105 6.974,0.105
VBIAS on Layer 8 "LAYER_8_VBIAS_P325" (solid, pour order 325): 90.97,0.022 92.361,0.022 93.908,1.57 93.908,7.879 93.095,8.693 71.987,8.693 71.518,6.854 71.518,-16.978 86.463,-16.978 86.463,0.058 86.5,0.022
VOUT on Layer 8 "LAYER_8_VOUT_P324" (solid, remove dead copper, pour order 324): 94.136,8.979 94.139,8.979 97.216,5.902 97.216,1.271 98.092,0.395 100.864,0.395 101.745,1.276 101.745,10.715 101.745,27.688 100.098,29.336 77.048,29.336 72.036,9.026
VSR on Layer 8 "LAYER_8_VSR_P289" (solid, remove dead copper, pour order 289): 61.303,1.857 70.846,1.857 71.315,2.326 71.315,6.854 76.847,29.373 77.05,29.538 89.258,29.553 100.265,29.553 101.745,31.02 101.745,66.254 100.455,67.544 60.72,67.544 60.72,2.44
VSEC+ on Layer 8 "LAYER_8_VSEC+_P244" (solid, pour order 244): 59.386,65.946 59.637,65.695 59.637,2.439 58.987,1.788 23.196,1.788 22.604,2.38 22.604,65.461 23.089,65.946
VSEC- on Layer 8 "LAYER_8_VSEC-_P240" (solid, pour order 240): 40.395,46.429 45.236,41.588 49.521,41.588 51.629,39.48 59.637,39.48 59.637,2.439 58.987,1.788 23.196,1.788 22.604,2.38 22.604,46.429
12V on Top Layer "TOP_LAYER_12V_P393" (solid, remove dead copper, pour order 393): -3.094,25.613 -3.094,27.95 -3.553,28.409 -6.902,28.409 -8.198,27.114 -8.131,1.486 -8.131,1.406 -7.304,0.579 8.769,0.579 9.944,1.754 9.944,14.016 9.419,14.542 -3.173,14.542 -3.538,14.906 -3.538,25.169
AGND on Top Layer "TOP_LAYER_AGND_P342" (solid, remove dead copper, pour order 342): 1.573,43.761 0.886,44.448 -3.956,44.448 -4.516,45.008 -4.516,55.347 -5.018,55.849 -7.181,55.849 -7.794,55.236 -7.794,43.602 -7.77,31.244 -6.014,29.488 0.937,29.488 0.937,29.434 1.573,30.071
NetC16_1 on Top Layer "TOP_LAYER_NETC16_1_P392" (solid, pour order 392): 5.93,8.206 5.93,3.479 5.412,2.96 5.332,3.04 4.682,3.04 4.452,3.271 4.465,3.284 4.465,5.74 3.665,6.54 3.665,8.357
NetD17_2 on Top Layer "TOP_LAYER_NETD17_2_P373" (solid, pour order 373): 2.735,9.499 2.952,9.282 5.658,9.282 5.831,9.454 5.831,10.348 5.625,10.555 2.96,10.555 2.735,10.33
VSEC+ on Top Layer "TOP_LAYER_VSEC+_P356" (solid, pour order 356): 5.464,62.123 4.226,62.123 3.903,62.425 3.903,65.831 4.034,65.963 8.317,65.963 8.453,65.826 8.453,65.204 8.347,65.098 5.94,65.098 5.799,64.957 5.799,62.457
VOUT on Top Layer "TOP_LAYER_VOUT_P338" (solid, remove dead copper, pour order 338): 95.16,8.976 95.16,7.828 97.215,5.772 97.215,1.24 98.06,0.395 100.898,0.395 101.745,1.242 101.745,28.269 100.679,29.336 77.048,29.336 72.036,9.026
DGND on Top Layer "TOP_LAYER_DGND_P387" (solid, remove dead copper, pour order 387): 3.846,58.51 3.846,55.94 4.069,55.718 5.533,55.718 5.66,55.845 5.66,58.654 3.99,58.654 3.862,58.526
VSEC- on Top Layer "TOP_LAYER_VSEC-_P372" (solid, pour order 372): 6.275,6.833 6.451,7.009 7.824,7.009 8.043,6.79 8.043,1.757 7.903,1.617 7.068,1.617 6.825,1.861 6.825,2.941 7.137,3.254 7.137,4.247 6.275,5.109
DGND on Top Layer "TOP_LAYER_DGND_P362" (solid, pour order 362): -4.068,45.364 -3.646,44.942 -1.908,44.942 -1.626,45.223 -1.626,55.27 -2.1,55.744 -3.61,55.744 -4.068,55.286
NetC2_1 on Top Layer "Top Layer-NetC2_1" (solid, pour order 361): 23 vertices, not listed, extent -1.415,56.721 8.678,63.647
12V on Top Layer "TOP_LAYER_12V_P359" (solid, pour order 359): 2.057,57.52 2.051,57.515 2.051,55.846 2.267,55.631 3.028,55.631 3.418,56.021 3.418,58.032 3.179,58.271 2.271,58.271 2.057,58.056
NetD15_2 on Top Layer "TOP_LAYER_NETD15_2_P358" (solid, pour order 358): 2.057,58.79 2.203,58.644 3.221,58.644 3.66,59.082 4.755,59.082 4.92,59.247 4.92,60.29 4.841,60.369 2.345,60.369 2.057,60.081
DGND on Top Layer "TOP_LAYER_DGND_P343" (solid, pour order 343): 17 vertices, not listed, extent -7.885,59.081 63.274,67.611
NetC29_1 on Top Layer "TOP_LAYER_NETC29_1_P355" (solid, pour order 355): -1.817,56.696 -3.249,56.696 -3.553,56.391 -4.985,56.391 -5.093,56.5 -5.093,58.664 -4.956,58.802 -1.958,58.802 -1.725,58.568 -1.725,56.788
VSEC+ on Top Layer "TOP_LAYER_VSEC+_P354" (solid, pour order 354): -7.843,56.717 -7.514,56.389 -5.503,56.389 -5.335,56.557 -5.335,58.68 -5.456,58.801 -7.529,58.801 -7.843,58.487
VSEC+ on Top Layer "TOP_LAYER_VSEC+_P262" (solid, pour order 262): 10.25,38.446 10.675,38.871 10.675,40.052 10.25,40.477 10.25,64.242 11.837,65.829 56.733,65.829 59.637,62.925 59.637,22.016 42.021,22.016 30.068,33.97 10.25,33.97
VBIAS on Top Layer "TOP_LAYER_VBIAS_P339" (solid, pour order 339): 93.893,3.56 93.893,7.917 93.095,8.693 71.987,8.693 71.518,6.854 71.518,-16.99 86.463,-16.967 86.463,0.058 86.5,0.022 92.346,0.022 93.893,1.569
DGND on Top Layer "TOP_LAYER_DGND_P220" (solid, remove dead copper, pour order 220): 20 vertices, not listed, extent 7.008,-17 62.38,2.941
VSR on Top Layer "TOP_LAYER_VSR_P301" (solid, remove dead copper, pour order 301): 18 vertices, not listed, extent 60.72,0.341 101.526,67.544
DGND on Top Layer "TOP_LAYER_DGND_P279" (solid, remove dead copper, pour order 279): 19.125,1.792 19.125,65.904 10.323,65.904 10.323,1.792
VSEC- on Top Layer "TOP_LAYER_VSEC-_P263" (solid, pour order 263): 22.604,33.794 10.256,33.794 10.256,2.692 10.811,2.137 58.275,2.137 59.637,3.499 59.637,61.277 58.519,62.395 22.604,62.395
NetC21_1 on Top Layer "TOP_LAYER_NETC21_1_P257" (solid, pour order 257): 2.433,15.12 2.72,14.833 6.667,14.833 9.425,17.591 9.425,22.487 6.684,25.228 2.764,25.228 2.433,24.897
NetC21_2 on Top Layer "TOP_LAYER_NETC21_2_P235" (solid, pour order 235): -1.158,15.101 -0.939,14.882 2.031,14.882 2.231,15.084 2.231,25.069 2.072,25.228 -0.976,25.228 -1.158,25.046
DGND on Top Layer "TOP_LAYER_DGND_P236" (solid, pour order 236): -3.005,25.228 -3.265,24.969 -3.265,15.16 -2.987,14.882 -1.678,14.882 -1.466,15.084 -1.466,25.156 -1.538,25.228
NetC6_1 on Top Layer "TOP_LAYER_NETC6_1_P256" (solid, pour order 256): 2.614,45.391 2.901,45.104 6.913,45.104 9.309,47.5 9.309,53.003 6.953,55.359 2.806,55.359 2.614,55.168
NetC6_2 on Top Layer "TOP_LAYER_NETC6_2_P232" (solid, pour order 232): -1.184,45.338 -0.95,45.104 1.996,45.104 2.191,45.284 2.191,55.098 1.93,55.359 -0.778,55.359 -1.184,54.953
DGND on Layer 7 "LAYER_7_DGND_P306" (solid, remove dead copper, pour order 306): 6.974,-16.999 22.001,-16.999 22.001,67.581 21.686,67.895 -8.263,67.895 -8.263,1.973 -6.395,0.105 6.974,0.105
VBIAS on Layer 7 "LAYER_7_VBIAS_P327" (solid, pour order 327): 90.97,0.022 91.285,0.337 92.691,0.337 93.908,1.555 93.908,7.879 93.095,8.693 71.987,8.693 71.518,6.854 71.518,-16.978 86.463,-16.978 86.463,0.058 86.5,0.022
VOUT on Layer 7 "LAYER_7_VOUT_P326" (solid, remove dead copper, pour order 326): 94.705,8.977 94.705,8.19 97.216,5.68 97.216,1.271 98.092,0.395 100.864,0.395 101.745,1.276 101.745,28.363 100.773,29.336 77.048,29.336 72.036,9.026
VSR on Layer 7 "LAYER_7_VSR_P291" (solid, remove dead copper, pour order 291): 70.609,1.857 71.315,2.563 71.315,6.854 76.847,29.373 77.05,29.538 100.823,29.554 101.746,30.477 101.746,65.843 100.045,67.544 60.72,67.544 60.72,2.443 60.72,2.432 61.297,1.857
VSEC- on Layer 7 "LAYER_7_VSEC-_P246" (solid, pour order 246): 59.386,65.946 59.637,65.695 59.637,2.439 58.987,1.788 23.196,1.788 22.604,2.38 22.604,65.461 23.089,65.946
VSEC+ on Layer 7 "LAYER_7_VSEC+_P241" (solid, pour order 241): 41.846,22.016 36.568,27.294 22.604,27.294 22.604,65.461 23.089,65.946 59.386,65.946 59.637,65.695 59.637,22.016
DGND on Layer 4 "LAYER_4_DGND_P303" (solid, remove dead copper, pour order 303): 25 vertices, not listed, extent -8.263,-16.999 63.14,67.895
VBIAS on Layer 4 "LAYER_4_VBIAS_P333" (solid, pour order 333): 93.894,1.57 93.894,7.894 93.095,8.693 71.987,8.693 71.518,6.854 71.518,-16.978 86.463,-16.955 86.463,0.058 86.5,0.022 92.346,0.022
VOUT on Layer 4 "LAYER_4_VOUT_P332" (solid, remove dead copper, pour order 332): 94.822,9.026 94.822,8.167 97.262,5.728 97.262,1.194 98.06,0.395 100.694,0.395 101.371,1.072 101.371,28.151 100.186,29.336 77.048,29.336 72.036,9.026
VSR on Layer 4 "LAYER_4_VSR_P296" (solid, remove dead copper, pour order 296): 60.72,63.932 64.332,67.544 99.588,67.544 101.746,65.387 101.746,30.992 100.294,29.554 77.05,29.538 76.847,29.373 71.103,5.993 71.103,0.645 63.683,0.645 60.72,3.608
VSEC+ on Layer 4 "LAYER_4_VSEC+_P253" (solid, pour order 253): 57.518,65.946 59.637,63.828 59.637,2.439 58.987,1.788 23.196,1.788 22.604,2.38 22.604,65.461 23.089,65.946
VSEC- on Layer 4 "LAYER_4_VSEC-_P252" (solid, pour order 252): 40.395,46.429 45.236,41.588 49.521,41.588 51.629,39.48 59.637,39.48 59.637,3.487 57.939,1.788 23.196,1.788 22.604,2.38 22.604,46.429
AGND on Bottom Layer "BOTTOM_LAYER_AGND_P394" (solid, remove dead copper, pour order 394): 7.365,34.905 7.365,36.432 8.151,37.218 11.663,37.218 11.747,37.134 11.738,37.125 11.738,36.263 10.108,34.634 7.646,34.634
AGND on Bottom Layer "BOTTOM_LAYER_AGND_P384" (solid, remove dead copper, pour order 384): 41 vertices, not listed, extent -8.222,2.268 8.739,48.319
VSEC- on Bottom Layer "BOTTOM_LAYER_VSEC-_P381" (solid, pour order 381): 17 vertices, not listed, extent 5.068,2.778 8.228,8.779
NetC16_1 on Bottom Layer "BOTTOM_LAYER_NETC16_1_P379" (solid, pour order 379): 17 vertices, not listed, extent 4,2.627 5.741,8.659
12V on Bottom Layer "BOTTOM_LAYER_12V_P375" (solid, pour order 375): 6.168,10.028 6.017,10.179 6.017,12.59 6.109,12.682 7.433,12.682 7.552,12.563 7.552,10.129 7.451,10.028
DGND on Bottom Layer "BOTTOM_LAYER_DGND_P374" (solid, pour order 374): 25 vertices, not listed, extent 1.247,10.048 7.442,15.043
DGND on Bottom Layer "BOTTOM_LAYER_DGND_P370" (solid, pour order 370): -3.502,45.932 -3.663,46.093 -3.663,47.764 -3.475,47.951 -2.944,47.951 -2.61,48.286 -2.61,48.803 -2.476,48.938 -1.798,48.938 -1.778,48.917 -1.758,48.917 -1.63,48.79 -1.63,46.167 -1.872,45.926 -3.468,45.926
DGND on Bottom Layer "BOTTOM_LAYER_DGND_P369" (solid, pour order 369): -3.486,52.634 -3.688,52.834 -3.688,54.287 -3.479,54.497 -1.878,54.497 -1.647,54.265 -1.647,50.715 -1.818,50.544 -2.561,50.544 -2.784,50.767 -2.784,52.279 -3.139,52.634
EN_SR1 on Bottom Layer "BOTTOM_LAYER_EN_SR1_P367" (solid, pour order 367): -7.728,46.863 -6.797,46.863 -6.566,47.094 -6.566,47.883 -6.872,48.189 -7.712,48.189 -7.857,48.044 -7.857,46.992
12V on Bottom Layer "BOTTOM_LAYER_12V_P366" (solid, pour order 366): 19 vertices, not listed, extent 1.823,52.365 7.787,56.417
